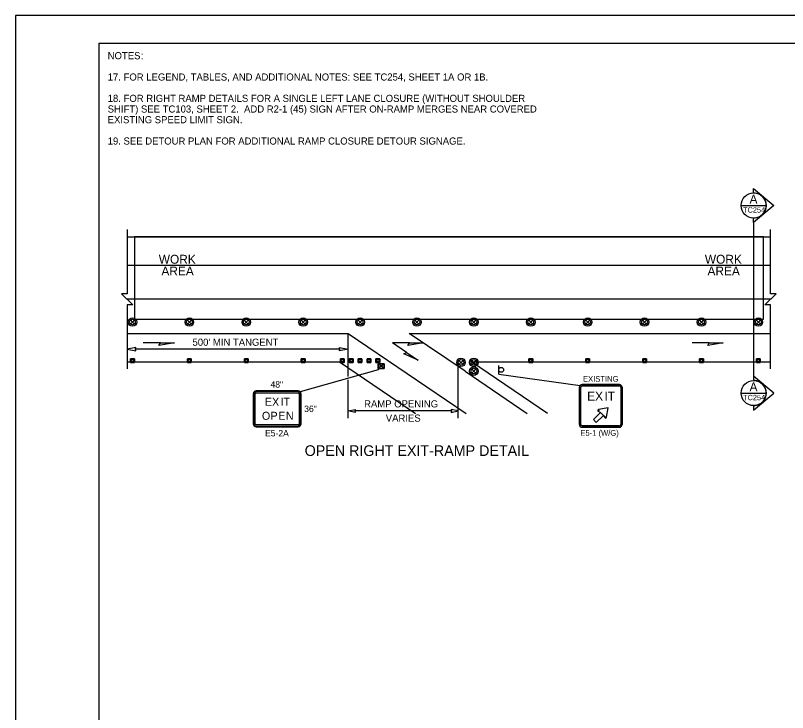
# Model space of a CAD drawing. Extents: x 99999 to 100116, y 99995 to 100013.
# Drawn here: x 100039.06 to 100047.75, y 100002.85 to 100010.69 of the extents above; entities that cross this region are included whole.
import ezdxf

# ---------------------------------------------------------------- set-up
doc = ezdxf.new("R2010")
doc.units = 0
for name, color, linetype in [('RD_MK_LineEdgeYellow', 7, 'Continuous'), ('RD_MK_LineLane', 7, 'Continuous'), ('SH_DE_DetailHeading2Text', 7, 'Continuous'), ('SH_GI_GeneralNotesBodyText', 7, 'Continuous'), ('SH_GI_PlotLimits', 7, 'Continuous'), ('SH_GI_SheetBorder', 7, 'Continuous'), ('SH_TI_WZSectionCut', 7, 'Continuous'), ('TR_SN_ConstructionSigns', 7, 'Continuous'), ('TR_WZ_PortableSignMount5ftMinBlk-Org', 7, 'Continuous'), ('TR_WZ_TrafficCone', 7, 'Continuous'), ('TR_WZ_TrafficSafetyDrum', 7, 'Continuous'), ('TR_WZ_WorkAreaLabel', 7, 'Continuous'), ('TR_WZ_WorkZoneDetails', 7, 'Continuous'), ('TR_WZ_WorkZoneTextCurrent', 7, 'Continuous')]:
    doc.layers.add(name, color=color, linetype=linetype)

msp = doc.modelspace()

# ---------------------------------------------------------------- linework, layer by layer
at = {"layer": 'RD_MK_LineEdgeYellow'}
for p, q in [((100040.32, 100007.8789), (100047.555, 100007.8789)), ((100040.32, 100007.1109), (100042.8064, 100007.1109)), ((100042.8064, 100007.1109), (100044.1333, 100006.2115)), ((100044.191, 100007.1109), (100047.555, 100007.1109)), ((100044.1192, 100006.685), (100044.8178, 100006.2115))]:
    msp.add_line(p, q, dxfattribs=at)
at = {"layer": 'RD_MK_LineLane'}
msp.add_lwpolyline([(100047.555, 100007.4949), (100040.32, 100007.4949)], dxfattribs=at)
at = {"layer": 'SH_GI_PlotLimits'}
msp.add_lwpolyline([(100039.0625, 99999.6875), (100056.0625, 99999.6875), (100056.0625, 100010.6875), (100039.0625, 100010.6875)], close=True, dxfattribs=at)
at = {"layer": 'SH_GI_SheetBorder'}
for q in [(100040, 100000), (100055.75, 100010.375)]:
    msp.add_line((100040, 100010.375), q, dxfattribs=at)
at = {"layer": 'SH_TI_WZSectionCut'}
for p, q in [((100047.3657, 100008.6913), (100047.3657, 100008.7412)), ((100047.3657, 100008.7412), (100047.5938, 100008.55)), ((100047.5938, 100008.55), (100047.3657, 100008.3589)), ((100047.3657, 100008.3589), (100047.3657, 100008.4088)), ((100047.3657, 100008.3589), (100047.3657, 100006.6309)), ((100047.3657, 100006.6309), (100047.3657, 100006.581)), ((100047.5939, 100006.4398), (100047.3657, 100006.6309)), ((100047.3657, 100006.2486), (100047.5939, 100006.4398)), ((100047.3657, 100006.2985), (100047.3657, 100006.2486))]:
    msp.add_line(p, q, dxfattribs=at)
for points in [[(100047.2245, 100008.5501), (100047.5069, 100008.5501)], [(100047.2245, 100006.4398), (100047.5069, 100006.4398)]]:
    msp.add_lwpolyline(points, dxfattribs=at)
for centre in [(100047.3657, 100008.55), (100047.3657, 100006.4398)]:
    msp.add_circle(centre, 0.1412, dxfattribs=at)
for centre in [(100047.3657, 100008.55), (100047.3657, 100006.4398)]:
    msp.add_arc(centre, 0.1412, 269.99779, 90.00221, dxfattribs=at)
at = {"layer": 'TR_SN_ConstructionSigns'}
for p, q in [((100045.4061, 100006.0854), (100045.4061, 100006.5054)), ((100045.4061, 100006.5054), (100045.4061, 100006.5054)), ((100045.4061, 100006.5054), (100045.4061, 100006.0854)), ((100045.4061, 100006.5054), (100045.4061, 100006.0854)), ((100045.4061, 100006.5054), (100045.4061, 100006.0854)), ((100045.4061, 100006.5054), (100045.4061, 100006.0854)), ((100045.4211, 100006.0854), (100045.4211, 100006.5054)), ((100045.4361, 100006.5354), (100045.8561, 100006.5354)), ((100045.8561, 100006.5354), (100045.4361, 100006.5354)), ((100045.8561, 100006.5354), (100045.4361, 100006.5354)), ((100045.8561, 100006.5354), (100045.4361, 100006.5354)), ((100045.8561, 100006.5354), (100045.4361, 100006.5354)), ((100045.4361, 100006.5204), (100045.8561, 100006.5204)), ((100045.8561, 100006.5354), (100045.8561, 100006.5354)), ((100045.8711, 100006.5054), (100045.8711, 100006.0854)), ((100045.8861, 100006.5054), (100045.8861, 100006.0854)), ((100045.8861, 100006.0854), (100045.8861, 100006.5054)), ((100045.8861, 100006.0854), (100045.8861, 100006.5054)), ((100045.8861, 100006.0854), (100045.8861, 100006.5054)), ((100045.8861, 100006.0854), (100045.8861, 100006.5054)), ((100041.7364, 100006.4318), (100041.7364, 100006.0943)), ((100041.7448, 100006.4318), (100041.7448, 100006.0943)), ((100041.7589, 100006.0943), (100041.7589, 100006.4318)), ((100042.2426, 100006.4656), (100041.7701, 100006.4656)), ((100042.2426, 100006.4571), (100041.7701, 100006.4571)), ((100041.7701, 100006.4431), (100042.2426, 100006.4431)), ((100042.2539, 100006.4318), (100042.2539, 100006.0943)), ((100042.268, 100006.0943), (100042.268, 100006.4318)), ((100042.2764, 100006.0943), (100042.2764, 100006.4318)), ((100045.6231, 100006.2462), (100045.618, 100006.2376)), ((100045.618, 100006.2376), (100045.6231, 100006.2462)), ((100045.7296, 100006.2758), (100045.6209, 100006.2559)), ((100045.6209, 100006.2559), (100045.6231, 100006.2462)), ((100045.6231, 100006.2462), (100045.6209, 100006.2559)), ((100045.7097, 100006.1671), (100045.7296, 100006.2758)), ((100045.643, 100006.2228), (100045.5625, 100006.1423)), ((100045.5961, 100006.1087), (100045.6765, 100006.1892)), ((100045.618, 100006.2376), (100045.643, 100006.2228)), ((100045.6765, 100006.1892), (100045.643, 100006.2228)), ((100045.643, 100006.2228), (100045.6765, 100006.1892)), ((100045.6765, 100006.1892), (100045.6914, 100006.1642)), ((100045.6914, 100006.1642), (100045.7, 100006.1693)), ((100045.7, 100006.1693), (100045.6914, 100006.1642)), ((100045.7, 100006.1693), (100045.7097, 100006.1671)), ((100045.7097, 100006.1671), (100045.7, 100006.1693)), ((100042.2426, 100006.0831), (100041.7701, 100006.0831)), ((100041.7701, 100006.069), (100042.2426, 100006.069)), ((100045.8561, 100006.0704), (100045.4361, 100006.0704)), ((100045.5625, 100006.1423), (100045.5961, 100006.1087)), ((100045.8861, 100006.0854), (100045.8861, 100006.0854)), ((100041.7701, 100006.0606), (100042.2426, 100006.0606)), ((100045.8561, 100006.0554), (100045.4361, 100006.0554)), ((100045.4361, 100006.0554), (100045.4361, 100006.0554)), ((100045.4361, 100006.0554), (100045.8561, 100006.0554)), ((100045.4361, 100006.0554), (100045.8561, 100006.0554)), ((100045.4361, 100006.0554), (100045.8561, 100006.0554))]:
    msp.add_line(p, q, dxfattribs=at)
for points in [[(100045.4361, 100006.0554), (100045.4361, 100006.0554)], [(100045.4361, 100006.0554), (100045.8561, 100006.0554), (100045.8561, 100006.0554)]]:
    msp.add_lwpolyline(points, dxfattribs=at)
for centre, radius, start, end in [((100045.4361, 100006.5054), 0.03, 90, 180.00001), ((100045.4361, 100006.5054), 0.03, 90, 180), ((100045.4361, 100006.5054), 0.03, 90, 180), ((100045.4361, 100006.5054), 0.03, 90, 180), ((100045.4361, 100006.5054), 0.03, 90, 180), ((100045.4361, 100006.5054), 0.015, 90, 180.00001), ((100045.8561, 100006.5054), 0.03, 0, 90), ((100045.8561, 100006.5054), 0.03, 0, 90), ((100045.8561, 100006.5054), 0.03, 0, 90), ((100045.8561, 100006.5054), 0.03, 0, 90), ((100045.8561, 100006.5054), 0.03, 0, 90), ((100045.8561, 100006.5054), 0.015, 0, 90), ((100041.7701, 100006.4318), 0.0338, 90, 180), ((100041.7701, 100006.4318), 0.0253, 90, 180.00001), ((100041.7701, 100006.4318), 0.0112, 90, 180.00001), ((100042.2426, 100006.4318), 0.0338, 360, 90), ((100042.2426, 100006.4318), 0.0253, 360, 90), ((100042.2426, 100006.4318), 0.0112, 360, 90), ((100045.6231, 100006.2462), 0.01, 102.77124, 239.32588), ((100045.7, 100006.1693), 0.01, 210.67414, 347.22877), ((100041.7701, 100006.0943), 0.0338, 180, 270.00001), ((100041.7701, 100006.0943), 0.0253, 180.00001, 270), ((100041.7701, 100006.0943), 0.0112, 180.00001, 270), ((100042.2426, 100006.0943), 0.0338, 270.00001, 0.00001), ((100042.2426, 100006.0943), 0.0253, 270, 0.00001), ((100042.2426, 100006.0943), 0.0112, 270, 0.00001), ((100045.4361, 100006.0854), 0.03, 180.00001, 270), ((100045.4361, 100006.0854), 0.03, 180, 270.00001), ((100045.4361, 100006.0854), 0.03, 180, 270.00001), ((100045.4361, 100006.0854), 0.03, 180, 270), ((100045.4361, 100006.0854), 0.03, 180, 270.00001), ((100045.4361, 100006.0854), 0.015, 180.00001, 270), ((100045.8561, 100006.0854), 0.03, 270, 0.00001), ((100045.8561, 100006.0854), 0.03, 270.00001, 0.00001), ((100045.8561, 100006.0854), 0.03, 270.00001, 0.00001), ((100045.8561, 100006.0854), 0.03, 270.00001, 0.00001), ((100045.8561, 100006.0854), 0.015, 270, 0.00001), ((100045.8561, 100006.0854), 0.03, 270.00001, 0.00001)]:
    msp.add_arc(centre, radius, start, end, dxfattribs=at)
at = {"layer": 'TR_WZ_PortableSignMount5ftMinBlk-Org'}
for p, q in [((100043.1433, 100006.7829), (100043.1433, 100006.7029)), ((100043.2101, 100006.7169), (100043.1433, 100006.7689)), ((100043.2101, 100006.7689), (100043.1433, 100006.7169)), ((100043.1767, 100006.7429), (100043.1767, 100006.7429)), ((100043.1768, 100006.7428), (100043.1768, 100006.7428))]:
    msp.add_line(p, q, dxfattribs=at)
for points in [[(100043.2101, 100006.7169), (100043.2101, 100006.7689), (100043.1433, 100006.7689), (100043.1433, 100006.7169)], [(100043.1433, 100006.7689), (100043.2101, 100006.7689), (100043.2101, 100006.7169), (100043.1433, 100006.7169)]]:
    msp.add_lwpolyline(points, close=True, dxfattribs=at)
at = {"layer": 'TR_WZ_TrafficCone'}
for points in [[(100040.3576, 100006.8256), (100040.4003, 100006.8256), (100040.4003, 100006.7829), (100040.3576, 100006.7829), (100040.3576, 100006.8256)], [(100040.3576, 100006.7829), (100040.4003, 100006.7829), (100040.4003, 100006.8256), (100040.3576, 100006.8256), (100040.3576, 100006.7829)], [(100040.9976, 100006.8256), (100041.0403, 100006.8256), (100041.0403, 100006.7829), (100040.9976, 100006.7829), (100040.9976, 100006.8256)], [(100040.9976, 100006.7829), (100041.0403, 100006.7829), (100041.0403, 100006.8256), (100040.9976, 100006.8256), (100040.9976, 100006.7829)], [(100041.6376, 100006.8256), (100041.6803, 100006.8256), (100041.6803, 100006.7829), (100041.6376, 100006.7829), (100041.6376, 100006.8256)], [(100041.6376, 100006.7829), (100041.6803, 100006.7829), (100041.6803, 100006.8256), (100041.6376, 100006.8256), (100041.6376, 100006.7829)], [(100042.2776, 100006.8256), (100042.3203, 100006.8256), (100042.3203, 100006.7829), (100042.2776, 100006.7829), (100042.2776, 100006.8256)], [(100042.2776, 100006.7829), (100042.3203, 100006.7829), (100042.3203, 100006.8256), (100042.2776, 100006.8256), (100042.2776, 100006.7829)], [(100042.7176, 100006.8256), (100042.7603, 100006.8256), (100042.7603, 100006.7829), (100042.7176, 100006.7829), (100042.7176, 100006.8256)], [(100042.7176, 100006.7829), (100042.7603, 100006.7829), (100042.7603, 100006.8256), (100042.7176, 100006.8256), (100042.7176, 100006.7829)], [(100042.8176, 100006.8256), (100042.8603, 100006.8256), (100042.8603, 100006.7829), (100042.8176, 100006.7829), (100042.8176, 100006.8256)], [(100042.8176, 100006.7829), (100042.8603, 100006.7829), (100042.8603, 100006.8256), (100042.8176, 100006.8256), (100042.8176, 100006.7829)], [(100042.9176, 100006.8256), (100042.9603, 100006.8256), (100042.9603, 100006.7829), (100042.9176, 100006.7829), (100042.9176, 100006.8256)], [(100042.9176, 100006.7829), (100042.9603, 100006.7829), (100042.9603, 100006.8256), (100042.9176, 100006.8256), (100042.9176, 100006.7829)], [(100043.0176, 100006.8256), (100043.0603, 100006.8256), (100043.0603, 100006.7829), (100043.0176, 100006.7829), (100043.0176, 100006.8256)], [(100043.0176, 100006.7829), (100043.0603, 100006.7829), (100043.0603, 100006.8256), (100043.0176, 100006.8256), (100043.0176, 100006.7829)], [(100043.1176, 100006.8256), (100043.1603, 100006.8256), (100043.1603, 100006.7829), (100043.1176, 100006.7829), (100043.1176, 100006.8256)], [(100043.1176, 100006.7829), (100043.1603, 100006.7829), (100043.1603, 100006.8256), (100043.1176, 100006.8256), (100043.1176, 100006.7829)], [(100044.8376, 100006.8256), (100044.8803, 100006.8256), (100044.8803, 100006.7829), (100044.8376, 100006.7829), (100044.8376, 100006.8256)], [(100044.8376, 100006.7829), (100044.8803, 100006.7829), (100044.8803, 100006.8256), (100044.8376, 100006.8256), (100044.8376, 100006.7829)], [(100045.4776, 100006.8256), (100045.5203, 100006.8256), (100045.5203, 100006.7829), (100045.4776, 100006.7829), (100045.4776, 100006.8256)], [(100045.4776, 100006.7829), (100045.5203, 100006.7829), (100045.5203, 100006.8256), (100045.4776, 100006.8256), (100045.4776, 100006.7829)], [(100046.1176, 100006.8256), (100046.1603, 100006.8256), (100046.1603, 100006.7829), (100046.1176, 100006.7829), (100046.1176, 100006.8256)], [(100046.1176, 100006.7829), (100046.1603, 100006.7829), (100046.1603, 100006.8256), (100046.1176, 100006.8256), (100046.1176, 100006.7829)], [(100046.7576, 100006.8256), (100046.8003, 100006.8256), (100046.8003, 100006.7829), (100046.7576, 100006.7829), (100046.7576, 100006.8256)], [(100046.7576, 100006.7829), (100046.8003, 100006.7829), (100046.8003, 100006.8256), (100046.7576, 100006.8256), (100046.7576, 100006.7829)], [(100047.3976, 100006.8256), (100047.4403, 100006.8256), (100047.4403, 100006.7829), (100047.3976, 100006.7829), (100047.3976, 100006.8256)], [(100047.3976, 100006.7829), (100047.4403, 100006.7829), (100047.4403, 100006.8256), (100047.3976, 100006.8256), (100047.3976, 100006.7829)]]:
    msp.add_lwpolyline(points, dxfattribs=at)
for centre in [(100040.3789, 100006.8042), (100041.0189, 100006.8042), (100041.6589, 100006.8042), (100042.2989, 100006.8042), (100042.7389, 100006.8042), (100042.8389, 100006.8042), (100042.9389, 100006.8042), (100043.0389, 100006.8042), (100043.1389, 100006.8042), (100044.8589, 100006.8042), (100045.4989, 100006.8042), (100046.1389, 100006.8042), (100046.7789, 100006.8042), (100047.4189, 100006.8042)]:
    msp.add_circle(centre, 0.0133, dxfattribs=at)
at = {"layer": 'TR_WZ_TrafficSafetyDrum'}
for p, q in [((100040.3563, 100007.2163), (100040.4015, 100007.2615)), ((100040.4015, 100007.2163), (100040.3563, 100007.2615)), ((100040.9963, 100007.2163), (100041.0415, 100007.2615)), ((100041.0415, 100007.2163), (100040.9963, 100007.2615)), ((100041.6363, 100007.2163), (100041.6815, 100007.2615)), ((100041.6815, 100007.2163), (100041.6363, 100007.2615)), ((100042.2763, 100007.2163), (100042.3215, 100007.2615)), ((100042.3215, 100007.2163), (100042.2763, 100007.2615)), ((100042.9163, 100007.2163), (100042.9615, 100007.2615)), ((100042.9615, 100007.2163), (100042.9163, 100007.2615)), ((100043.5563, 100007.2163), (100043.6015, 100007.2615)), ((100043.6015, 100007.2163), (100043.5563, 100007.2615)), ((100044.1963, 100007.2163), (100044.2415, 100007.2615)), ((100044.2415, 100007.2163), (100044.1963, 100007.2615)), ((100044.8363, 100007.2163), (100044.8815, 100007.2615)), ((100044.8815, 100007.2163), (100044.8363, 100007.2615)), ((100045.4763, 100007.2163), (100045.5215, 100007.2615)), ((100045.5215, 100007.2163), (100045.4763, 100007.2615)), ((100046.1163, 100007.2163), (100046.1615, 100007.2615)), ((100046.1615, 100007.2163), (100046.1163, 100007.2615)), ((100046.7563, 100007.2163), (100046.8015, 100007.2615)), ((100046.8015, 100007.2163), (100046.7563, 100007.2615)), ((100047.3963, 100007.2163), (100047.4415, 100007.2615)), ((100047.4415, 100007.2163), (100047.3963, 100007.2615)), ((100044.0513, 100006.7629), (100044.0965, 100006.8082)), ((100044.0965, 100006.7629), (100044.0513, 100006.8082)), ((100044.1963, 100006.7629), (100044.2415, 100006.8082)), ((100044.2415, 100006.7629), (100044.1963, 100006.8082)), ((100044.1963, 100006.6647), (100044.2415, 100006.7099)), ((100044.2415, 100006.6647), (100044.1963, 100006.7099))]:
    msp.add_line(p, q, dxfattribs=at)
for centre, radius in [((100040.3789, 100007.2389), 0.048), ((100040.3789, 100007.2389), 0.048), ((100041.0189, 100007.2389), 0.048), ((100041.0189, 100007.2389), 0.048), ((100041.6589, 100007.2389), 0.048), ((100041.6589, 100007.2389), 0.048), ((100042.2989, 100007.2389), 0.048), ((100042.2989, 100007.2389), 0.048), ((100042.9389, 100007.2389), 0.048), ((100042.9389, 100007.2389), 0.048), ((100043.5789, 100007.2389), 0.048), ((100043.5789, 100007.2389), 0.048), ((100044.2189, 100007.2389), 0.048), ((100044.2189, 100007.2389), 0.048), ((100044.8589, 100007.2389), 0.048), ((100044.8589, 100007.2389), 0.048), ((100045.4989, 100007.2389), 0.048), ((100045.4989, 100007.2389), 0.048), ((100046.1389, 100007.2389), 0.048), ((100046.1389, 100007.2389), 0.048), ((100046.7789, 100007.2389), 0.048), ((100046.7789, 100007.2389), 0.048), ((100047.4189, 100007.2389), 0.048), ((100047.4189, 100007.2389), 0.048), ((100040.3789, 100007.2389), 0.032), ((100041.0189, 100007.2389), 0.032), ((100041.6589, 100007.2389), 0.032), ((100042.2989, 100007.2389), 0.032), ((100042.9389, 100007.2389), 0.032), ((100043.5789, 100007.2389), 0.032), ((100044.2189, 100007.2389), 0.032), ((100044.8589, 100007.2389), 0.032), ((100045.4989, 100007.2389), 0.032), ((100046.1389, 100007.2389), 0.032), ((100046.7789, 100007.2389), 0.032), ((100047.4189, 100007.2389), 0.032), ((100044.0739, 100006.7856), 0.048), ((100044.0739, 100006.7856), 0.048), ((100044.0739, 100006.7856), 0.032), ((100044.2189, 100006.7856), 0.048), ((100044.2189, 100006.7856), 0.048), ((100044.2189, 100006.7856), 0.032), ((100044.2189, 100006.6873), 0.048), ((100044.2189, 100006.6873), 0.048), ((100044.2189, 100006.6873), 0.032)]:
    msp.add_circle(centre, radius, dxfattribs=at)
at = {"layer": 'TR_WZ_WorkZoneDetails'}
for p, q in [((100040.32, 100008.1989), (100047.555, 100008.1989)), ((100042.8064, 100006.6279), (100042.8064, 100007.1109)), ((100043.4908, 100007.1109), (100044.191, 100007.1109)), ((100044.1192, 100006.685), (100043.4908, 100007.1109)), ((100042.7126, 100006.934), (100040.4137, 100006.934)), ((100040.6926, 100007.0048), (100040.4997, 100007.0048)), ((100043.4618, 100006.8966), (100043.3021, 100007.0048)), ((100043.495, 100007.0048), (100043.3021, 100007.0048)), ((100046.8669, 100007.0048), (100046.674, 100007.0048)), ((100040.32, 100006.7909), (100042.7081, 100006.7909)), ((100042.7081, 100006.7909), (100043.563, 100006.2115)), ((100044.0419, 100006.1585), (100044.0419, 100006.7856)), ((100044.191, 100006.7909), (100047.555, 100006.7909)), ((100045.0455, 100006.2115), (100044.191, 100006.7909)), ((100043.1433, 100006.7029), (100042.2665, 100006.4557)), ((100044.4984, 100006.651), (100044.4984, 100006.751)), ((100042.8064, 100006.1585), (100042.8064, 100006.5879)), ((100044.4984, 100006.651), (100045.4148, 100006.5266)), ((100043.9669, 100006.2385), (100042.8814, 100006.2385))]:
    msp.add_line(p, q, dxfattribs=at)
for points in [[(100040.32, 100008.2789), (100040.32, 100007.5569), (100040.256, 100007.5569), (100040.384, 100007.433), (100040.32, 100007.433), (100040.32, 100006.7109)], [(100047.555, 100006.7109), (100047.555, 100007.433), (100047.491, 100007.433), (100047.619, 100007.5569), (100047.555, 100007.5569), (100047.555, 100008.2789)]]:
    msp.add_lwpolyline(points, dxfattribs=at)
for points in [[(100040.4, 100008.1989), (100040.4, 100007.2709), (100047.475, 100007.2709), (100047.475, 100008.1989)], [(100040.32, 100006.934), (100040.4183, 100006.9147), (100040.4137, 100006.934), (100040.4183, 100006.9532)], [(100040.8498, 100007.0048), (100040.6747, 100006.974), (100040.6926, 100007.0048)], [(100042.8063, 100006.934), (100042.7081, 100006.9147), (100042.7126, 100006.934), (100042.7081, 100006.9532)], [(100043.6523, 100007.0048), (100043.4772, 100006.974), (100043.495, 100007.0048)], [(100047.0241, 100007.0048), (100046.849, 100006.974), (100046.8669, 100007.0048)], [(100043.592, 100006.8084), (100043.4297, 100006.8811), (100043.4618, 100006.8966)], [(100042.8064, 100006.2385), (100042.885, 100006.2539), (100042.8814, 100006.2385), (100042.885, 100006.2231)], [(100044.0419, 100006.2385), (100043.9633, 100006.2539), (100043.9669, 100006.2385), (100043.9633, 100006.2231)]]:
    msp.add_lwpolyline(points, close=True, dxfattribs=at)
msp.add_circle((100044.5254, 100006.701), 0.027, dxfattribs=at)
msp.add_circle((100044.5254, 100006.701), 0.027, dxfattribs=at)

# ---------------------------------------------------------------- texts
at = {"layer": 'SH_DE_DetailHeading2Text'}
msp.add_text('OPEN RIGHT EXIT-RAMP DETAIL', height=0.12, rotation=360, dxfattribs=at).set_placement((100042.3159, 100005.7326))
at = {"layer": 'SH_GI_GeneralNotesBodyText'}
for s, p in [('NOTES', (100040.1, 100010.195)), (':', (100040.4743, 100010.195)), ('17. FOR LEGEND, TABLES, AND ADDITIONAL NOTES: SEE TC254, SHEET 1A OR 1B.', (100040.1, 100009.955)), ('18. FOR RIGHT RAMP DETAILS FOR A SINGLE LEFT LANE CLOSURE (WITHOUT SHOULDER ', (100040.1, 100009.715)), ('SHIFT) SEE TC103, SHEET 2.  ADD R2-1 (45) SIGN AFTER ON-RAMP MERGES NEAR COVERED ', (100040.1, 100009.595)), ('EXISTING SPEED LIMIT SIGN.', (100040.1, 100009.475)), ('19. SEE DETOUR PLAN FOR ADDITIONAL RAMP CLOSURE DETOUR SIGNAGE.', (100040.1, 100009.235))]:
    msp.add_text(s, height=0.08, rotation=360, dxfattribs=at).set_placement(p)
at = {"layer": 'SH_TI_WZSectionCut'}
for s, height, rotation, p in [('A', 0.1, 0.00995, (100047.3195, 100008.5707)), ('TC254', 0.06, 360, (100047.2464, 100008.4701)), ('A', 0.1, 0.00995, (100047.3195, 100006.4604)), ('TC254', 0.06, 360, (100047.2464, 100006.3598))]:
    msp.add_text(s, height=height, rotation=rotation, dxfattribs=at).set_placement(p)
at = {"layer": 'TR_SN_ConstructionSigns'}
for s, height, p in [('EXISTING', 0.064, (100045.4462, 100006.5674)), ('48"', 0.072, (100041.9316, 100006.5016)), ('E', 0.09, (100041.8687, 100006.2968)), ('X', 0.09, (100041.9488, 100006.2968)), ('I', 0.09, (100042.0451, 100006.2968)), ('T', 0.09, (100042.0766, 100006.2968)), ('36"', 0.072, (100042.3102, 100006.2271)), ('O', 0.09, (100041.8349, 100006.1393)), ('P', 0.09, (100041.9312, 100006.1393)), ('E', 0.09, (100042.0194, 100006.1393)), ('N', 0.09, (100042.1049, 100006.1393)), ('E5-2A', 0.072, (100041.8698, 100005.9526)), ('E5-1 (W/G)', 0.064, (100045.4161, 100005.9594))]:
    msp.add_text(s, height=height, rotation=360, dxfattribs=at).set_placement(p)
for s, p in [('E', (100045.4931, 100006.3558)), ('X', (100045.5821, 100006.3558)), ('I', (100045.6891, 100006.3558)), ('T', (100045.7241, 100006.3558))]:
    msp.add_text(s, height=0.1, dxfattribs=at).set_placement(p)
at = {"layer": 'TR_WZ_WorkAreaLabel'}
for s, p in [('WORK', (100040.6746, 100007.8949)), ('WORK', (100046.8169, 100007.8949)), ('AREA', (100040.7043, 100007.7629)), ('AREA', (100046.8465, 100007.7629))]:
    msp.add_text(s, height=0.1, dxfattribs=at).set_placement(p)
at = {"layer": 'TR_WZ_WorkZoneTextCurrent'}
for s, p in [("500' MIN TANGENT", (100041.0542, 100006.972)), ('RAMP OPENING', (100042.9842, 100006.2785)), ('VARIES', (100043.2279, 100006.1185))]:
    msp.add_text(s, height=0.08, dxfattribs=at).set_placement(p)

doc.saveas('drawing.dxf')
